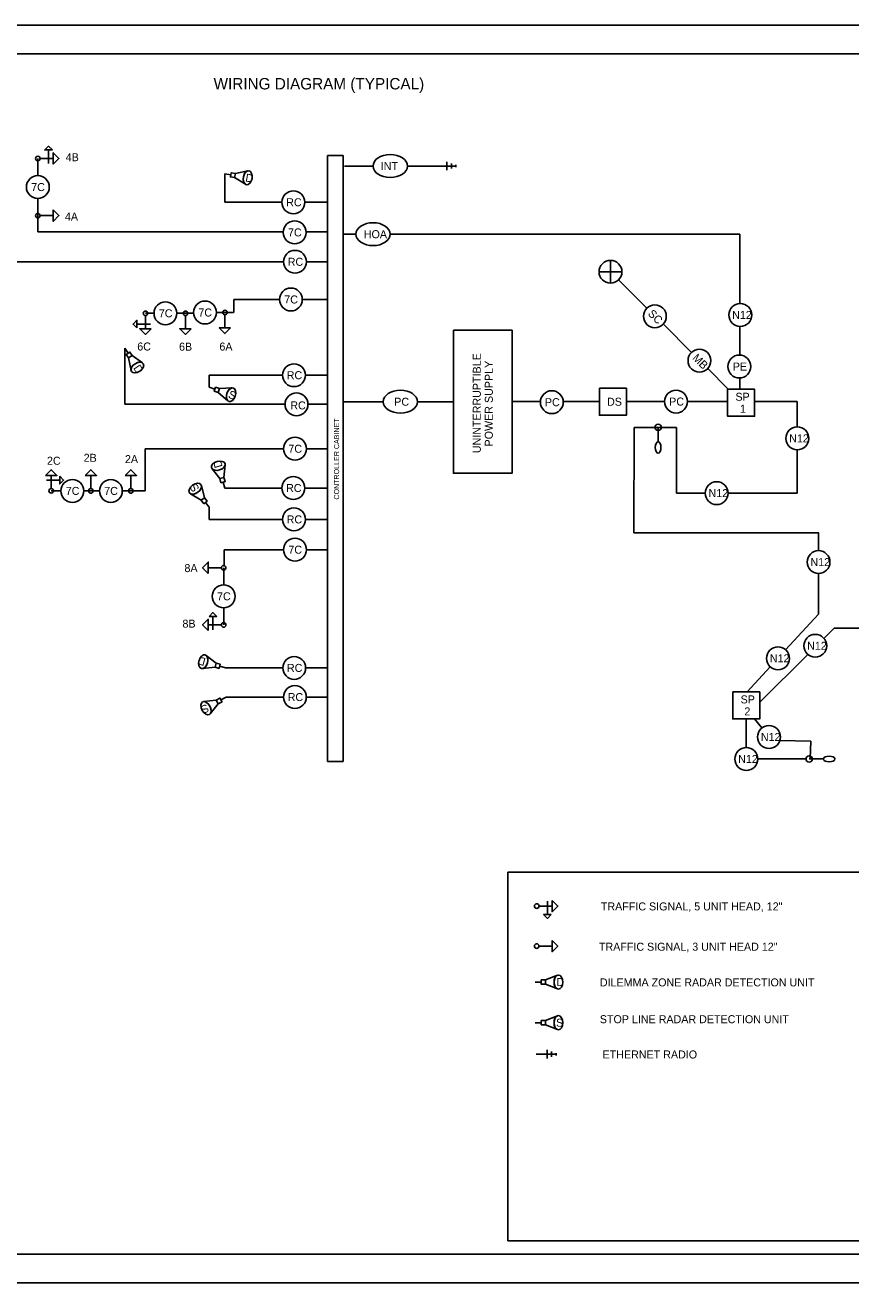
# Model space of a CAD drawing. Extents: x 32.6 to 95.8, y 11.4 to 49.5.
# Drawn here: x 46.65 to 61.1, y 27.47 to 49.47 of the extents above; entities that cross this region are included whole.
import ezdxf

# ---------------------------------------------------------------- set-up
doc = ezdxf.new("R2010")
doc.units = 0
for name, color, linetype in [('LT_P_Luminaires', 7, 'Continuous'), ('SG_P_Detection', 7, 'Continuous'), ('SG_P_Heads', 7, 'Continuous'), ('SG_P_Interconnect_Cable', 7, 'Continuous'), ('SG_P_Text', 7, 'Continuous'), ('SH_Border', 7, 'Continuous'), ('SH_Cut_Line', 7, 'Continuous'), ('SH_Data', 7, 'Continuous'), ('SH_Text', 7, 'Continuous')]:
    doc.layers.add(name, color=color, linetype=linetype)

msp = doc.modelspace()

# ---------------------------------------------------------------- linework, layer by layer
at = {"layer": 'LT_P_Luminaires'}
for p, q in [((57.727, 42.435), (57.727, 42.185)), ((60.37, 36.635), (60.62, 36.635))]:
    msp.add_line(p, q, dxfattribs=at)
for centre in [(57.727, 42.435), (60.37, 36.635)]:
    msp.add_circle(centre, 0.055, dxfattribs=at)
for centre, major_axis in [((57.727, 42.085), (0, -0.1)), ((60.72, 36.635), (0.1, 0))]:
    msp.add_ellipse(centre, major_axis=major_axis, ratio=0.5, dxfattribs=at)
at = {"layer": 'SG_P_Detection'}
for p, q in [((50.145, 46.873), (50.25, 46.854)), ((50.33, 46.878), (50.317, 46.804)), ((50.317, 46.804), (50.33, 46.878)), ((50.33, 46.878), (50.547, 46.923)), ((50.547, 46.923), (50.33, 46.878)), ((50.317, 46.804), (50.505, 46.687)), ((50.317, 46.804), (50.505, 46.687)), ((48.394, 43.822), (48.452, 43.733)), ((48.524, 43.691), (48.462, 43.65)), ((48.462, 43.65), (48.524, 43.691)), ((48.462, 43.65), (48.504, 43.432)), ((48.462, 43.65), (48.504, 43.432)), ((48.524, 43.691), (48.706, 43.563)), ((48.706, 43.563), (48.524, 43.691)), ((49.871, 43.137), (49.971, 43.103)), ((50.054, 43.114), (50.276, 43.127)), ((50.276, 43.127), (50.054, 43.114)), ((50.054, 43.114), (50.03, 43.043)), ((50.03, 43.043), (50.199, 42.899)), ((50.03, 43.043), (50.199, 42.899)), ((50.058, 41.539), (49.921, 41.713)), ((49.921, 41.713), (50.058, 41.539)), ((50.13, 41.56), (50.152, 41.78)), ((50.13, 41.56), (50.152, 41.78)), ((49.791, 41.205), (49.734, 41.419)), ((49.791, 41.205), (49.734, 41.419)), ((50.058, 41.539), (50.13, 41.56)), ((50.13, 41.56), (50.058, 41.539)), ((50.144, 41.375), (50.115, 41.477)), ((49.731, 41.16), (49.542, 41.275)), ((49.542, 41.275), (49.731, 41.16)), ((49.731, 41.16), (49.791, 41.205)), ((49.869, 41.037), (49.806, 41.122)), ((49.994, 38.312), (49.818, 38.447)), ((49.994, 38.312), (49.818, 38.447)), ((49.974, 38.24), (49.994, 38.312)), ((49.994, 38.312), (49.974, 38.24)), ((49.974, 38.24), (49.754, 38.216)), ((49.754, 38.216), (49.974, 38.24)), ((50.159, 38.228), (50.056, 38.256)), ((49.995, 37.664), (49.774, 37.638)), ((49.995, 37.664), (49.774, 37.638)), ((50.031, 37.598), (49.995, 37.664)), ((50.171, 37.718), (50.078, 37.667)), ((50.031, 37.598), (49.89, 37.427)), ((49.89, 37.427), (50.031, 37.598)), ((55.758, 32.77), (55.964, 32.852)), ((55.964, 32.852), (55.758, 32.77)), ((55.577, 32.732), (55.683, 32.732)), ((55.758, 32.77), (55.758, 32.695)), ((55.758, 32.695), (55.758, 32.77)), ((55.758, 32.695), (55.964, 32.612)), ((55.758, 32.695), (55.964, 32.612)), ((55.758, 32.06), (55.964, 32.142)), ((55.964, 32.142), (55.758, 32.06)), ((55.577, 32.022), (55.683, 32.022)), ((55.758, 32.06), (55.758, 31.985)), ((55.758, 31.985), (55.964, 31.902)), ((55.758, 31.985), (55.964, 31.902))]:
    msp.add_line(p, q, dxfattribs=at)
for points in [[(50.256, 46.891), (50.243, 46.817), (50.317, 46.804), (50.33, 46.878)], [(48.484, 43.753), (48.421, 43.713), (48.462, 43.65), (48.524, 43.691)], [(49.983, 43.139), (49.959, 43.067), (50.03, 43.043), (50.054, 43.114)], [(50.078, 41.467), (50.151, 41.487), (50.13, 41.56), (50.058, 41.539)], [(49.776, 41.1), (49.836, 41.144), (49.791, 41.205), (49.731, 41.16)], [(50.046, 38.22), (50.066, 38.292), (49.994, 38.312), (49.974, 38.24)], [(50.096, 37.634), (50.06, 37.7), (49.995, 37.664), (50.031, 37.598)], [(55.683, 32.77), (55.683, 32.695), (55.758, 32.695), (55.758, 32.77)], [(55.683, 32.06), (55.683, 31.985), (55.758, 31.985), (55.758, 32.06)]]:
    msp.add_lwpolyline(points, close=True, dxfattribs=at)
for points in [[(50.33, 46.878), (50.256, 46.891), (50.243, 46.817), (50.317, 46.804)], [(48.524, 43.691), (48.484, 43.753), (48.421, 43.713), (48.462, 43.65)], [(49.983, 43.139), (49.959, 43.067), (50.03, 43.043), (50.054, 43.114), (49.983, 43.139)], [(50.058, 41.539), (50.078, 41.467), (50.151, 41.487), (50.13, 41.56)], [(49.776, 41.1), (49.836, 41.144), (49.791, 41.205), (49.731, 41.16), (49.776, 41.1)], [(49.974, 38.24), (50.046, 38.22), (50.066, 38.292), (49.994, 38.312)], [(50.096, 37.634), (50.06, 37.7), (49.995, 37.664), (50.031, 37.598), (50.096, 37.634)], [(55.758, 32.77), (55.683, 32.77), (55.683, 32.695), (55.758, 32.695)], [(55.683, 32.06), (55.683, 31.985), (55.758, 31.985), (55.758, 32.06), (55.683, 32.06)]]:
    msp.add_lwpolyline(points, dxfattribs=at)
for centre, major_axis in [((50.545, 46.802), (-0.022, -0.122)), ((48.615, 43.482), (-0.104, -0.067)), ((50.255, 43.007), (-0.04, -0.117)), ((50.031, 41.765), (0.119, 0.034)), ((49.627, 41.362), (0.0993, 0.0741)), ((49.768, 38.337), (0.033, 0.119)), ((49.816, 37.523), (-0.06, 0.109)), ((55.982, 32.732), (0, -0.124)), ((55.982, 32.022), (0, -0.124))]:
    msp.add_ellipse(centre, major_axis=major_axis, ratio=0.621318, dxfattribs=at)
for centre, major_axis in [((50.545, 46.802), (-0.022, -0.122)), ((48.615, 43.482), (-0.104, -0.067)), ((50.255, 43.007), (-0.04, -0.117)), ((50.031, 41.765), (0.119, 0.034)), ((49.627, 41.362), (0.0993, 0.0741)), ((49.768, 38.337), (0.033, 0.119)), ((49.816, 37.523), (-0.06, 0.109)), ((55.982, 32.732), (0, -0.124)), ((55.982, 32.022), (0, -0.124))]:
    msp.add_ellipse(centre, major_axis=major_axis, ratio=0.621318, start_param=3.386213, end_param=6.038231, dxfattribs=at)
at = {"layer": 'SG_P_Heads'}
for p, q in [((46.913, 47.139), (47.143, 47.139)), ((47.062, 47.053), (47.062, 47.288)), ((46.913, 46.139), (47.143, 46.139)), ((48.842, 44.242), (48.607, 44.242)), ((48.756, 44.391), (48.756, 44.161)), ((49.456, 44.391), (49.456, 44.161)), ((50.148, 44.405), (50.148, 44.175)), ((47.108, 41.365), (47.108, 41.595)), ((47.801, 41.364), (47.801, 41.594)), ((48.501, 41.364), (48.501, 41.594)), ((47.022, 41.514), (47.257, 41.514)), ((50.085, 39.98), (49.855, 39.98)), ((50.085, 38.98), (49.855, 38.98)), ((49.936, 38.894), (49.936, 39.129)), ((55.792, 34.148), (55.792, 33.913)), ((55.643, 34.062), (55.873, 34.062)), ((55.642, 33.362), (55.872, 33.362))]:
    msp.add_line(p, q, dxfattribs=at)
for points in [[(47.128, 47.288), (47.061, 47.354), (46.995, 47.288)], [(47.143, 47.039), (47.243, 47.139), (47.143, 47.239)], [(47.143, 46.239), (47.243, 46.139), (47.143, 46.039)], [(48.607, 44.176), (48.54, 44.243), (48.607, 44.309)], [(48.856, 44.161), (48.756, 44.061), (48.656, 44.161)], [(49.556, 44.161), (49.456, 44.061), (49.356, 44.161)], [(50.247, 44.175), (50.147, 44.075), (50.047, 44.175)], [(47.007, 41.594), (47.107, 41.694), (47.207, 41.594)], [(47.701, 41.594), (47.801, 41.694), (47.901, 41.594)], [(48.401, 41.594), (48.501, 41.694), (48.601, 41.594)], [(47.256, 41.58), (47.323, 41.513), (47.256, 41.446)], [(49.855, 39.88), (49.755, 39.98), (49.855, 40.08)], [(49.87, 39.129), (49.937, 39.196), (50.004, 39.129)], [(49.856, 38.88), (49.756, 38.98), (49.856, 39.08)], [(55.872, 34.162), (55.972, 34.062), (55.872, 33.962)], [(55.858, 33.913), (55.791, 33.846), (55.724, 33.913)], [(55.871, 33.462), (55.971, 33.362), (55.871, 33.262)]]:
    msp.add_lwpolyline(points, close=True, dxfattribs=at)
for centre in [(46.873, 47.139), (46.873, 46.139), (48.756, 44.431), (49.456, 44.431), (50.148, 44.445), (47.108, 41.325), (47.801, 41.324), (48.501, 41.324), (50.125, 39.98), (50.125, 38.98), (55.603, 34.062), (55.602, 33.362)]:
    msp.add_circle(centre, 0.04, dxfattribs=at)
at = {"layer": 'SG_P_Interconnect_Cable'}
for p, q in [((54.029, 46.932), (54.029, 47.082)), ((53.839, 47.007), (54.189, 47.007)), ((54.109, 46.962), (54.109, 47.052)), ((54.189, 47.027), (54.189, 46.987)), ((55.594, 31.471), (55.944, 31.471)), ((55.784, 31.396), (55.784, 31.546)), ((55.864, 31.426), (55.864, 31.516)), ((55.944, 31.491), (55.944, 31.451))]:
    msp.add_line(p, q, dxfattribs=at)
at = {"layer": 'SG_P_Text'}
for p, q in [((52.439, 45.815), (52.212, 45.815)), ((53.266, 45.815), (53.039, 45.815)), ((56.893, 44.957), (56.893, 45.357)), ((57.093, 45.157), (56.693, 45.157)), ((52.918, 42.884), (52.691, 42.884)), ((53.745, 42.884), (53.518, 42.884))]:
    msp.add_line(p, q, dxfattribs=at)
for points in [[(56.699, 43.121), (57.173, 43.121), (57.173, 42.647), (56.699, 42.647)], [(58.942, 43.103), (59.416, 43.103), (59.416, 42.629), (58.942, 42.629)], [(58.942, 43.103), (59.416, 43.103), (59.416, 42.629), (58.942, 42.629)], [(59.033, 37.809), (59.506, 37.809), (59.506, 37.335), (59.033, 37.335)]]:
    msp.add_lwpolyline(points, close=True, dxfattribs=at)
for centre in [(46.873, 46.639), (51.345, 46.373), (51.367, 45.846), (51.373, 45.332), (56.893, 45.157), (51.301, 44.673), (49.106, 44.431), (49.798, 44.445), (57.67, 44.379), (59.164, 44.402), (58.45, 43.603), (59.148, 43.5), (51.355, 43.348), (51.399, 42.839), (55.867, 42.876), (58.041, 42.887), (51.373, 42.062), (60.162, 42.243), (47.478, 41.324), (48.151, 41.324), (51.344, 41.375), (58.751, 41.285), (51.354, 40.826), (51.373, 40.296), (60.534, 40.079), (50.125, 39.48), (60.476, 38.615), (59.824, 38.395), (51.359, 38.228), (51.371, 37.718), (59.667, 37.02), (59.27, 36.635)]:
    msp.add_circle(centre, 0.2, dxfattribs=at)
for centre in [(53.039, 47.007), (52.739, 45.815), (53.218, 42.884)]:
    msp.add_ellipse(centre, major_axis=(0.3, 0), ratio=0.666667, dxfattribs=at)
at = {"layer": 'SH_Border'}
msp.add_lwpolyline([(44.837, 48.971), (76.337, 48.971), (76.337, 27.971), (44.837, 27.971)], close=True, dxfattribs=at)
at = {"layer": 'SH_Cut_Line'}
msp.add_lwpolyline([(42.837, 27.471), (76.837, 27.471), (76.837, 49.471), (42.837, 49.471)], close=True, dxfattribs=at)
at = {"layer": 'SH_Data'}
for p, q in [((46.873, 47.139), (46.873, 46.839)), ((51.94, 47.194), (51.94, 36.593)), ((52.213, 47.194), (51.94, 47.194)), ((52.213, 36.593), (52.213, 47.194)), ((50.145, 46.873), (50.145, 46.373)), ((52.239, 47.007), (52.739, 47.007)), ((53.339, 47.007), (53.839, 47.007)), ((46.873, 46.439), (46.873, 46.139)), ((51.145, 46.373), (50.145, 46.373)), ((51.94, 46.373), (51.545, 46.373)), ((46.873, 46.139), (46.873, 45.856)), ((51.167, 45.856), (46.873, 45.856)), ((51.94, 45.856), (51.567, 45.856)), ((52.439, 45.815), (52.213, 45.815)), ((59.157, 45.815), (53.039, 45.815)), ((59.157, 45.815), (59.157, 44.602)), ((51.173, 45.332), (45.673, 45.332)), ((51.94, 45.332), (51.573, 45.332)), ((57.529, 44.52), (57.034, 45.015)), ((51.101, 44.673), (50.301, 44.673)), ((50.301, 44.445), (50.301, 44.673)), ((51.94, 44.673), (51.501, 44.673)), ((49.998, 44.445), (50.148, 44.445)), ((50.148, 44.445), (50.298, 44.445)), ((48.906, 44.431), (48.756, 44.431)), ((49.306, 44.431), (49.456, 44.431)), ((49.456, 44.431), (49.606, 44.431)), ((58.313, 43.746), (57.818, 44.241)), ((59.157, 44.202), (59.157, 43.7)), ((48.394, 42.839), (48.394, 43.822)), ((51.155, 43.348), (49.871, 43.348)), ((49.871, 43.137), (49.871, 43.348)), ((51.94, 43.348), (51.555, 43.348)), ((58.948, 43.111), (58.596, 43.463)), ((59.157, 43.3), (59.157, 43.119)), ((51.199, 42.839), (48.394, 42.839)), ((51.94, 42.839), (51.599, 42.839)), ((52.213, 42.884), (52.691, 42.884)), ((53.745, 42.884), (54.145, 42.884)), ((55.171, 42.887), (55.667, 42.887)), ((56.067, 42.887), (56.699, 42.887)), ((57.841, 42.887), (57.173, 42.887)), ((58.942, 42.887), (58.241, 42.887)), ((60.16, 42.887), (59.416, 42.887)), ((60.16, 42.887), (60.16, 42.443)), ((57.305, 42.435), (57.3, 40.589)), ((57.305, 42.435), (58.051, 42.435)), ((58.051, 41.285), (58.051, 42.435)), ((51.173, 42.062), (48.751, 42.062)), ((48.751, 41.324), (48.751, 42.062)), ((51.94, 42.062), (51.573, 42.062)), ((60.16, 42.043), (60.16, 41.285)), ((51.144, 41.375), (50.144, 41.375)), ((51.94, 41.375), (51.544, 41.375)), ((47.278, 41.324), (47.108, 41.324)), ((47.951, 41.324), (47.678, 41.324)), ((48.351, 41.324), (48.501, 41.324)), ((48.501, 41.324), (48.751, 41.324)), ((58.551, 41.285), (58.051, 41.285)), ((60.16, 41.285), (58.951, 41.285)), ((49.869, 40.826), (49.869, 41.037)), ((51.154, 40.826), (49.869, 40.826)), ((51.94, 40.826), (51.554, 40.826)), ((60.538, 40.589), (57.3, 40.589)), ((60.534, 40.589), (60.534, 40.279)), ((51.173, 40.296), (50.133, 40.296)), ((50.133, 40.002), (50.133, 40.296)), ((51.94, 40.296), (51.573, 40.296)), ((50.125, 39.68), (50.125, 39.98)), ((60.533, 39.879), (60.531, 39.169)), ((50.125, 38.98), (50.125, 39.28)), ((60.531, 39.169), (59.958, 38.544)), ((60.809, 38.924), (60.628, 38.745)), ((62.505, 38.924), (60.809, 38.924)), ((60.346, 38.463), (59.506, 37.627)), ((51.159, 38.228), (50.159, 38.228)), ((51.94, 38.228), (51.559, 38.228)), ((59.688, 38.249), (59.285, 37.809)), ((51.171, 37.718), (50.171, 37.718)), ((51.94, 37.718), (51.571, 37.718)), ((59.27, 37.335), (59.27, 36.835)), ((59.412, 37.335), (59.543, 37.177)), ((60.396, 36.944), (59.858, 36.96)), ((60.396, 36.944), (60.386, 36.636)), ((51.94, 36.593), (52.213, 36.593)), ((59.47, 36.635), (60.315, 36.635))]:
    msp.add_line(p, q, dxfattribs=at)
for points in [[(54.145, 44.134), (55.171, 44.134), (55.171, 41.634), (54.145, 41.634)], [(55.099, 34.655), (74.956, 34.655), (74.956, 28.209), (55.099, 28.209)]]:
    msp.add_lwpolyline(points, close=True, dxfattribs=at)

# ---------------------------------------------------------------- texts
at = {"layer": 'SG_P_Detection'}
for s, rotation, p in [('D', 349.8821, (50.497, 46.739)), ('D', 302.9955, (48.537, 43.473)), ('S', 341.3227, (50.194, 42.954)), ('D', 106.1868, (50.108, 41.75)), ('S', 126.7526, (49.707, 41.371)), ('D', 164.4585, (49.821, 38.395)), ('S', 208.7489, (49.818, 37.604))]:
    msp.add_text(s, height=0.14, rotation=rotation, dxfattribs=at).set_placement(p)
for s, p in [('D', (55.947, 32.662)), ('S', (55.941, 31.952))]:
    msp.add_text(s, height=0.14, dxfattribs=at).set_placement(p)
at = {"layer": 'SG_P_Text'}
for s, rotation, p in [('INT', 360, (52.873, 46.937)), ('7C', 360, (46.757, 46.569)), ('RC', 360, (51.219, 46.303)), ('7C', 360, (51.251, 45.776)), ('RC', 360, (51.246, 45.262)), ('7C', 360, (51.185, 44.603)), ('7C', 360, (48.99, 44.361)), ('7C', 360, (49.682, 44.375)), ('SC', 315, (57.538, 44.413)), ('MB', 315, (58.316, 43.638)), ('PE', 360, (59.033, 43.43)), ('RC', 360, (51.228, 43.278)), ('PC', 360, (55.746, 42.806)), ('PC', 360, (57.92, 42.817)), ('RC', 360, (51.291, 42.75)), ('7C', 360, (51.257, 41.992)), ('7C', 360, (47.362, 41.254)), ('7C', 360, (48.035, 41.254)), ('RC', 360, (51.217, 41.305)), ('RC', 360, (51.227, 40.756)), ('7C', 360, (51.257, 40.226)), ('7C', 360, (50.009, 39.41)), ('RC', 360, (51.232, 38.158)), ('RC', 360, (51.245, 37.648))]:
    msp.add_text(s, height=0.14, rotation=rotation, dxfattribs=at).set_placement(p)
for s, p in [('HOA', (52.577, 45.745)), ('N12', (59.022, 44.332)), ('PC', (53.109, 42.814)), ('DS', (56.833, 42.814)), ('SP', (59.08, 42.901)), ('SP', (59.08, 42.901)), ('1', (59.158, 42.691)), ('1', (59.158, 42.691)), ('N12', (60.02, 42.173)), ('N12', (58.609, 41.215)), ('N12', (60.392, 40.009)), ('N12', (60.334, 38.545)), ('N12', (59.682, 38.325)), ('SP', (59.17, 37.607)), ('2', (59.236, 37.397)), ('N12', (59.525, 36.95)), ('N12', (59.127, 36.565))]:
    msp.add_text(s, height=0.14, dxfattribs=at).set_placement(p)
at = {"layer": 'SH_Text'}
for s, height, p in [('WIRING DIAGRAM (TYPICAL)', 0.2, (49.949, 48.347)), ('4B', 0.14, (47.361, 47.091)), ('4A', 0.14, (47.347, 46.052)), ('6C', 0.14, (48.613, 43.78)), ('6B', 0.14, (49.344, 43.777)), ('6A', 0.14, (50.05, 43.779)), ('TRAFFIC SIGNAL, 5 UNIT HEAD, 12"', 0.14, (56.725, 33.986)), ('TRAFFIC SIGNAL, 3 UNIT HEAD 12"', 0.14, (56.691, 33.281)), ('DILEMMA ZONE RADAR DETECTION UNIT', 0.14, (56.708, 32.657)), ('STOP LINE RADAR DETECTION UNIT', 0.14, (56.707, 32.013)), ('ETHERNET RADIO', 0.14, (56.755, 31.396))]:
    msp.add_text(s, height=height, dxfattribs=at).set_placement(p)
for s, height, rotation, p in [('UNINTERRUPTIBLE', 0.14, 90, (54.624, 41.985)), ('POWER SUPPLY', 0.14, 90, (54.834, 42.102)), ('CONTROLLER CABINET', 0.08993, 90, (52.145, 41.172)), ('2C', 0.14, 360, (47.033, 41.782)), ('2B', 0.14, 360, (47.675, 41.833)), ('2A', 0.14, 360, (48.397, 41.811)), ('8A', 0.14, 360, (49.439, 39.904)), ('8B', 0.14, 360, (49.404, 38.932))]:
    msp.add_text(s, height=height, rotation=rotation, dxfattribs=at).set_placement(p)

doc.saveas('drawing.dxf')
